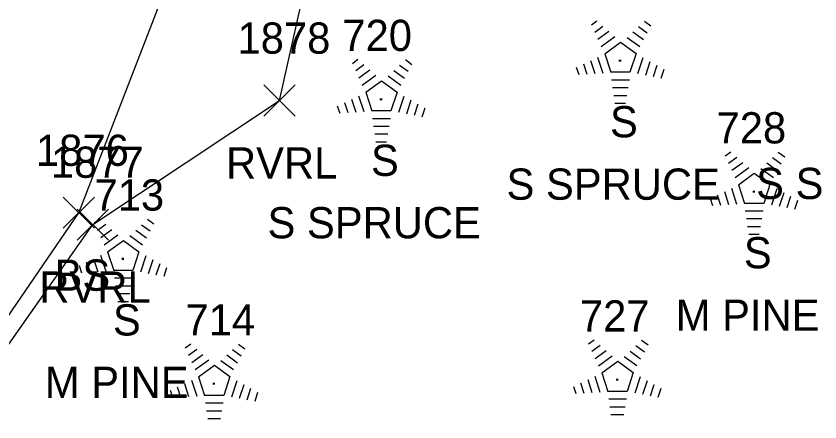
# Model space of a CAD drawing. Extents: x 1545627 to 1546562, y 571176 to 576667.
# Drawn here: x 1546211.1 to 1546262.6, y 572214.6 to 572240.6 of the extents above; entities that cross this region are included whole.
import ezdxf

# ---------------------------------------------------------------- set-up
doc = ezdxf.new("R2010")
doc.units = 0
for name, color, linetype in [('L_A', 7, 'Continuous'), ('L_C', 7, 'Continuous'), ('L_I', 7, 'Continuous'), ('L_TIC', 7, 'Continuous'), ('LAWE', 7, 'Continuous'), ('LELB', 7, 'Continuous'), ('LTC', 7, 'Continuous')]:
    doc.layers.add(name, color=color, linetype=linetype)

msp = doc.modelspace()

# ---------------------------------------------------------------- linework, layer by layer
at = {"layer": 'L_TIC'}
for points in [[(1546227.024, 572234.176), (1546229.024, 572236.176)], [(1546229.024, 572234.176), (1546227.024, 572236.176)], [(1546214.164, 572226.989), (1546216.164, 572228.989)], [(1546216.164, 572226.989), (1546214.164, 572228.989)], [(1546215.066, 572226.226), (1546217.066, 572228.226)], [(1546217.066, 572226.226), (1546215.066, 572228.226)]]:
    msp.add_lwpolyline(points, dxfattribs=at)
at = {"layer": 'LAWE'}
msp.add_lwpolyline([(1546121.265, 571957.172), (1546118.803, 571996.677), (1546114.937, 572038.101), (1546108, 572065.636), (1546104.767, 572084.584), (1546111.687, 572095.842), (1546118.703, 572113.935), (1546133.848, 572134.836), (1546145.167, 572135.646), (1546153.927, 572139.019), (1546169.651, 572160.036), (1546189.008, 572163.697), (1546206.714, 572193.958), (1546205.832, 572212.69), (1546216.066, 572227.226), (1546228.024, 572235.176), (1546234.868, 572265.766), (1546262.797, 572295.702), (1546275.487, 572309.557), (1546290.065, 572324.25)], dxfattribs=at)
at = {"layer": 'LELB'}
msp.add_lwpolyline([(1546138.465, 572142.662), (1546151.843, 572140.861), (1546169.324, 572161.725), (1546185.772, 572170.699), (1546202.895, 572194.936), (1546204.894, 572212.997), (1546215.164, 572227.989), (1546230.472, 572267.575), (1546260.052, 572296.387), (1546273.8, 572312.974), (1546290.068, 572327.618), (1546314.576, 572291.02)], dxfattribs=at)
at = {"layer": 'LTC'}
for p, q in [((1546248.007, 572240.028), (1546248.362, 572240.285)), ((1546251.405, 572240.268), (1546251.825, 572239.964)), ((1546248.217, 572239.562), (1546248.746, 572239.947)), ((1546248.426, 572239.097), (1546249.13, 572239.608)), ((1546250.663, 572239.572), (1546251.343, 572239.078)), ((1546251.034, 572239.92), (1546251.584, 572239.521)), ((1546248.636, 572238.631), (1546249.514, 572239.269)), ((1546250.292, 572239.223), (1546251.102, 572238.634)), ((1546248.86, 572238.176), (1546249.872, 572238.91)), ((1546249.872, 572238.91), (1546250.869, 572238.185)), ((1546248.86, 572238.176), (1546249.248, 572236.982)), ((1546250.869, 572238.185), (1546250.478, 572236.982)), ((1546232.692, 572237.556), (1546233.047, 572237.814)), ((1546232.902, 572237.091), (1546233.431, 572237.475)), ((1546236.091, 572237.796), (1546236.51, 572237.492)), ((1546247.495, 572237.524), (1546247.707, 572236.872)), ((1546247.95, 572237.74), (1546248.222, 572236.905)), ((1546248.406, 572237.957), (1546248.737, 572236.937)), ((1546251.307, 572237.914), (1546250.969, 572236.875)), ((1546251.751, 572237.664), (1546251.464, 572236.779)), ((1546233.111, 572236.625), (1546233.815, 572237.136)), ((1546235.348, 572237.1), (1546236.028, 572236.606)), ((1546235.719, 572237.448), (1546236.269, 572237.049)), ((1546247.04, 572237.307), (1546247.192, 572236.839)), ((1546250.478, 572236.982), (1546249.248, 572236.982)), ((1546252.196, 572237.414), (1546251.959, 572236.684)), ((1546252.64, 572237.164), (1546252.453, 572236.589)), ((1546233.321, 572236.159), (1546234.199, 572236.797)), ((1546233.546, 572235.704), (1546234.557, 572236.439)), ((1546234.557, 572236.439), (1546235.554, 572235.714)), ((1546234.977, 572236.751), (1546235.787, 572236.163)), ((1546250.44, 572236.482), (1546249.295, 572236.482)), ((1546250.356, 572235.982), (1546249.368, 572235.982)), ((1546233.091, 572235.485), (1546233.422, 572234.466)), ((1546233.546, 572235.704), (1546233.933, 572234.511)), ((1546235.554, 572235.714), (1546235.163, 572234.511)), ((1546235.992, 572235.443), (1546235.654, 572234.403)), ((1546250.272, 572235.482), (1546249.44, 572235.482)), ((1546232.18, 572235.052), (1546232.392, 572234.4)), ((1546232.636, 572235.269), (1546232.907, 572234.433)), ((1546236.436, 572235.192), (1546236.149, 572234.308)), ((1546236.881, 572234.942), (1546236.644, 572234.213)), ((1546250.188, 572234.982), (1546249.513, 572234.982)), ((1546231.725, 572234.835), (1546231.877, 572234.367)), ((1546235.163, 572234.511), (1546233.933, 572234.511)), ((1546237.325, 572234.692), (1546237.138, 572234.118)), ((1546235.125, 572234.011), (1546233.98, 572234.011)), ((1546235.041, 572233.511), (1546234.053, 572233.511)), ((1546234.957, 572233.011), (1546234.126, 572233.011)), ((1546234.873, 572232.511), (1546234.198, 572232.511)), ((1546256.581, 572231.635), (1546256.936, 572231.892)), ((1546259.98, 572231.875), (1546260.399, 572231.571)), ((1546256.791, 572231.169), (1546257.32, 572231.554)), ((1546259.609, 572231.527), (1546260.158, 572231.128)), ((1546257.001, 572230.704), (1546257.704, 572231.215)), ((1546257.21, 572230.238), (1546258.089, 572230.876)), ((1546258.866, 572230.83), (1546259.676, 572230.241)), ((1546259.238, 572231.179), (1546259.917, 572230.685)), ((1546257.435, 572229.783), (1546258.446, 572230.517)), ((1546258.446, 572230.517), (1546259.444, 572229.792)), ((1546257.435, 572229.783), (1546257.822, 572228.589)), ((1546259.444, 572229.792), (1546259.052, 572228.589)), ((1546256.525, 572229.347), (1546256.796, 572228.512)), ((1546256.98, 572229.564), (1546257.311, 572228.544)), ((1546259.881, 572229.521), (1546259.543, 572228.482)), ((1546260.326, 572229.271), (1546260.038, 572228.386)), ((1546255.614, 572228.914), (1546255.766, 572228.446)), ((1546256.069, 572229.131), (1546256.281, 572228.479)), ((1546260.77, 572229.021), (1546260.533, 572228.291)), ((1546261.214, 572228.771), (1546261.028, 572228.196)), ((1546259.052, 572228.589), (1546257.822, 572228.589)), ((1546259.014, 572228.089), (1546257.869, 572228.089)), ((1546216.155, 572227.331), (1546216.51, 572227.589)), ((1546216.365, 572226.866), (1546216.894, 572227.25)), ((1546219.182, 572227.223), (1546219.732, 572226.824)), ((1546219.553, 572227.572), (1546219.973, 572227.267)), ((1546258.93, 572227.589), (1546257.942, 572227.589)), ((1546216.574, 572226.4), (1546217.278, 572226.911)), ((1546218.811, 572226.875), (1546219.491, 572226.381)), ((1546258.846, 572227.089), (1546258.015, 572227.089)), ((1546216.784, 572225.934), (1546217.662, 572226.572)), ((1546217.008, 572225.479), (1546218.02, 572226.214)), ((1546218.02, 572226.214), (1546219.017, 572225.489)), ((1546218.44, 572226.527), (1546219.25, 572225.938)), ((1546258.763, 572226.589), (1546258.088, 572226.589)), ((1546216.554, 572225.26), (1546216.885, 572224.241)), ((1546217.008, 572225.479), (1546217.396, 572224.286)), ((1546219.017, 572225.489), (1546218.626, 572224.286)), ((1546219.455, 572225.218), (1546219.117, 572224.178)), ((1546215.188, 572224.61), (1546215.34, 572224.142)), ((1546215.643, 572224.827), (1546215.855, 572224.175)), ((1546216.098, 572225.044), (1546216.37, 572224.208)), ((1546219.899, 572224.967), (1546219.612, 572224.083)), ((1546220.344, 572224.717), (1546220.107, 572223.988)), ((1546218.626, 572224.286), (1546217.396, 572224.286)), ((1546220.788, 572224.467), (1546220.601, 572223.893)), ((1546218.588, 572223.786), (1546217.443, 572223.786)), ((1546218.504, 572223.286), (1546217.516, 572223.286)), ((1546218.42, 572222.786), (1546217.588, 572222.786)), ((1546218.336, 572222.286), (1546217.661, 572222.286)), ((1546221.985, 572219.332), (1546222.339, 572219.589)), ((1546225.383, 572219.572), (1546225.802, 572219.268)), ((1546247.827, 572219.587), (1546248.181, 572219.844)), ((1546248.036, 572219.121), (1546248.565, 572219.505)), ((1546250.854, 572219.479), (1546251.403, 572219.079)), ((1546251.225, 572219.827), (1546251.644, 572219.522)), ((1546222.194, 572218.866), (1546222.723, 572219.251)), ((1546222.404, 572218.401), (1546223.108, 572218.912)), ((1546225.012, 572219.224), (1546225.561, 572218.825)), ((1546248.246, 572218.655), (1546248.949, 572219.167)), ((1546250.483, 572219.13), (1546251.162, 572218.637)), ((1546222.613, 572217.935), (1546223.492, 572218.573)), ((1546224.27, 572218.527), (1546225.079, 572217.938)), ((1546224.641, 572218.876), (1546225.32, 572218.382)), ((1546248.455, 572218.189), (1546249.334, 572218.827)), ((1546248.68, 572217.734), (1546249.692, 572218.469)), ((1546249.692, 572218.469), (1546250.689, 572217.744)), ((1546250.112, 572218.782), (1546250.921, 572218.193)), ((1546222.838, 572217.48), (1546223.85, 572218.214)), ((1546223.85, 572218.214), (1546224.847, 572217.489)), ((1546222.838, 572217.48), (1546223.225, 572216.286)), ((1546224.847, 572217.489), (1546224.455, 572216.286)), ((1546248.225, 572217.515), (1546248.556, 572216.496)), ((1546248.68, 572217.734), (1546249.067, 572216.541)), ((1546250.689, 572217.744), (1546250.297, 572216.541)), ((1546251.126, 572217.473), (1546250.788, 572216.434)), ((1546221.928, 572217.044), (1546222.199, 572216.209)), ((1546222.383, 572217.261), (1546222.714, 572216.241)), ((1546225.284, 572217.218), (1546224.946, 572216.179)), ((1546225.729, 572216.968), (1546225.441, 572216.083)), ((1546246.859, 572216.866), (1546247.011, 572216.398)), ((1546247.314, 572217.082), (1546247.526, 572216.431)), ((1546247.77, 572217.299), (1546248.041, 572216.464)), ((1546251.571, 572217.223), (1546251.283, 572216.338)), ((1546252.015, 572216.973), (1546251.778, 572216.243)), ((1546221.017, 572216.611), (1546221.169, 572216.143)), ((1546221.473, 572216.828), (1546221.684, 572216.176)), ((1546226.173, 572216.718), (1546225.936, 572215.988)), ((1546226.618, 572216.468), (1546226.431, 572215.893)), ((1546250.297, 572216.541), (1546249.067, 572216.541)), ((1546252.459, 572216.722), (1546252.273, 572216.148)), ((1546224.455, 572216.286), (1546223.225, 572216.286)), ((1546250.259, 572216.041), (1546249.114, 572216.041)), ((1546224.417, 572215.786), (1546223.273, 572215.786)), ((1546250.175, 572215.541), (1546249.187, 572215.541)), ((1546224.333, 572215.286), (1546223.345, 572215.286)), ((1546250.092, 572215.041), (1546249.26, 572215.041)), ((1546224.25, 572214.786), (1546223.418, 572214.786))]:
    msp.add_line(p, q, dxfattribs=at)

# ---------------------------------------------------------------- texts
at = {"layer": 'L_A'}
for s, p in [('S', (1546249.198, 572232.82)), ('S', (1546233.883, 572230.348)), ('RVRL', (1546224.591, 572230.176)), ('S', (1546257.772, 572224.427)), ('BS', (1546213.605, 572222.989)), ('RVRL', (1546212.633, 572222.226)), ('S', (1546217.346, 572220.123))]:
    msp.add_text(s, height=2, dxfattribs=at).set_placement(p)
at = {"layer": 'L_C'}
for s, p in [('S SPRUCE', (1546242.568, 572228.82)), ('S SPRUCE', (1546258.563, 572228.864)), ('S SPRUCE', (1546227.253, 572226.348)), ('M PINE', (1546253.41, 572220.427)), ('M PINE', (1546212.984, 572216.123))]:
    msp.add_text(s, height=2, dxfattribs=at).set_placement(p)
at = {"layer": 'L_I'}
for s, p in [('1878', (1546225.331, 572238.176)), ('720', (1546232.048, 572238.348)), ('728', (1546256.024, 572232.427)), ('1876', (1546212.416, 572230.989)), ('1877', (1546213.373, 572230.226)), ('713', (1546216.165, 572228.123)), ('714', (1546221.994, 572220.124)), ('727', (1546247.269, 572220.378))]:
    msp.add_text(s, height=2, dxfattribs=at).set_placement(p)
at = {"layer": 'LTC'}
for p in [(1546249.755, 572237.924), (1546234.44, 572235.452), (1546258.329, 572229.531), (1546217.903, 572225.227), (1546223.732, 572217.228), (1546249.574, 572217.482)]:
    msp.add_text('.', height=1.037, rotation=270, dxfattribs=at).set_placement(p)

doc.saveas('drawing.dxf')
